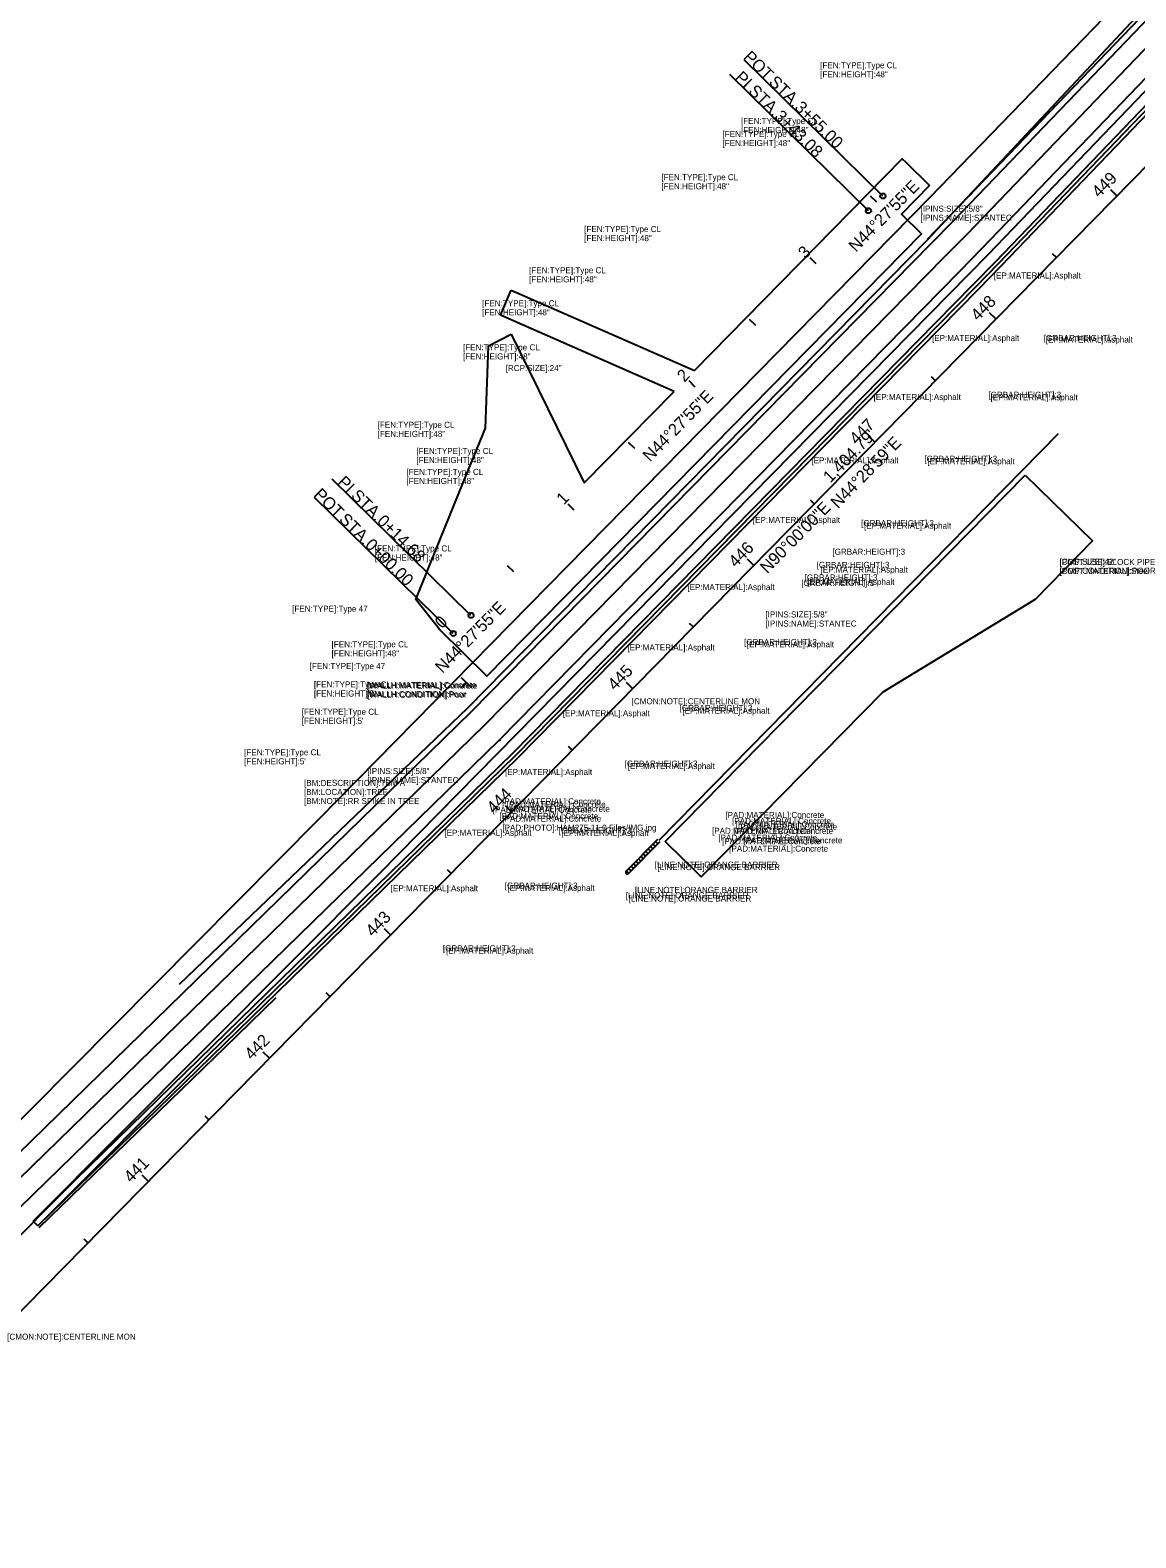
# Model space of a CAD drawing. Extents: x 142554 to 147512, y 370190 to 373751.
# Drawn here: x 144390 to 145029, y 370980 to 371853 of the extents above; entities that cross this region are included whole.
import ezdxf

# ---------------------------------------------------------------- set-up
doc = ezdxf.new("R2010")
doc.units = 0
for name, color, linetype in [('DR_P_Cells', 7, 'Continuous'), ('DR_P_Storm_Sewer', 7, 'Continuous'), ('DR_X_Cells', 7, 'Continuous'), ('DR_X_Ditch', 7, 'Continuous'), ('DR_X_GenericNode', 7, 'Continuous'), ('FeatureService_Stream Network', 7, 'Continuous'), ('FeatureService_Water Bodies', 7, 'Continuous'), ('GE_P_Alignment', 7, 'Continuous'), ('PF_X_Ground_Line', 7, 'Continuous'), ('PM_X_Edge_Line', 7, 'Continuous'), ('PM_X_Lane_Line', 7, 'Continuous'), ('PV_X_EOP', 7, 'Continuous'), ('PV_X_Field_Drive', 7, 'Continuous'), ('PV_X_Shoulder', 7, 'Continuous'), ('RD_X_Fence', 7, 'Continuous'), ('RD_X_GR_Cable_Bar', 7, 'Continuous'), ('RD_X_GR_Lt', 7, 'Continuous'), ('RD_X_GR_Rt', 7, 'Continuous'), ('SC_Scratch20', 7, 'Continuous'), ('UT_X_Electric_Cells', 7, 'Continuous')]:
    doc.layers.add(name, color=color, linetype=linetype)

msp = doc.modelspace()

# ---------------------------------------------------------------- linework, layer by layer
at = {"layer": 'DR_P_Cells'}
for points in [[(144375.11, 371179.46), (144652.68, 371450.31), (144919.03, 371721.55), (144931.96, 371734.79), (145131.57, 371942.86), (145332.92, 372147.7)], [(144383.56, 371170.93), (144661.15, 371441.81), (144927.61, 371713.15), (144940.58, 371726.45), (145140.18, 371934.5), (145341.48, 372139.29)]]:
    msp.add_lwpolyline(points, dxfattribs=at)
at = {"layer": 'DR_P_Storm_Sewer'}
for p, q in [((144734.5, 371365.75), (144752.79, 371384.23)), ((144735.92, 371364.35), (144754.21, 371382.82)), ((144745.78, 371374.31), (144744.36, 371375.71)), ((144747.19, 371375.73), (144745.77, 371377.14)), ((144748.6, 371377.15), (144747.17, 371378.56)), ((144750, 371378.57), (144748.58, 371379.98)), ((144751.41, 371379.99), (144749.99, 371381.4)), ((144752.82, 371381.41), (144751.4, 371382.82)), ((144737.34, 371365.78), (144735.92, 371367.19)), ((144738.75, 371367.2), (144737.33, 371368.61)), ((144740.15, 371368.62), (144738.73, 371370.03)), ((144741.56, 371370.04), (144740.14, 371371.45)), ((144742.97, 371371.46), (144741.55, 371372.87)), ((144744.38, 371372.89), (144742.95, 371374.29)), ((144735.93, 371364.36), (144734.51, 371365.76))]:
    msp.add_line(p, q, dxfattribs=at)
msp.add_arc((144735.22, 371365.05), 1, 135.74249, 315.74249, dxfattribs=at)
at = {"layer": 'DR_X_Cells'}
for p, q in [((144908.94, 371731.25), (145224.54, 372068.86)), ((144908.94, 371731.25), (144642.69, 371460.12)), ((144753.5, 371383.53), (144984.75, 371619.21)), ((144642.69, 371460.12), (144475.78, 371300.04))]:
    msp.add_line(p, q, dxfattribs=at)
at = {"layer": 'DR_X_Ditch'}
for p, q in [((144661.78, 371687.66), (144668.02, 371702.23)), ((144668.02, 371702.23), (144774.04, 371655.59)), ((144762.2, 371643.53), (144661.78, 371687.66)), ((144667.85, 371676.73), (144710.2, 371590.55)), ((144710.2, 371590.55), (144762.2, 371643.53)), ((144757.03, 371382.87), (144965.48, 371595.07))]:
    msp.add_line(p, q, dxfattribs=at)
for points in [[(144774.04, 371655.59), (144894.32, 371778.14), (144896.46, 371776.03), (144910.06, 371762.69), (144893.79, 371746.13), (144905.37, 371734.75), (144653.84, 371478.61), (144626.59, 371505.36), (144612.82, 371523.05), (144626.7, 371557.33), (144640.3, 371591.06), (144653.05, 371622.21), (144654.77, 371669.83), (144667.85, 371676.73)], [(144965.48, 371595.07), (145004.38, 371556.87), (144971.13, 371523.01), (144883.07, 371469.33), (144777.96, 371362.31), (144757.03, 371382.87)]]:
    msp.add_lwpolyline(points, dxfattribs=at)
at = {"layer": 'DR_X_GenericNode'}
msp.add_line((144209.21, 370979.55), (144416.12, 371187.34), dxfattribs=at)
for points in [[(144342.37, 371162.87), (144644.83, 371458.02), (144911.08, 371729.15), (144923.95, 371742.35), (145123.58, 371950.42), (145324.99, 372155.32)], [(144416.12, 371187.34), (144668.82, 371433.92), (144935.38, 371705.37), (144948.4, 371718.72), (145147.98, 371926.75), (145349.23, 372131.49)]]:
    msp.add_lwpolyline(points, dxfattribs=at)
at = {"layer": 'FeatureService_Stream Network'}
msp.add_lwpolyline([(145322.49, 372157.77), (145121.08, 371952.87), (144908.69, 371731.49)], dxfattribs=at)
at = {"layer": 'FeatureService_Water Bodies'}
msp.add_line((144394.01, 371160.17), (144492.32, 371258.89), dxfattribs=at)
msp.add_line((144394.01, 371160.17), (144492.32, 371258.89), dxfattribs=at)
for points in [[(145352.09, 372128.68), (145150.85, 371923.96), (144951.28, 371715.94), (144938.24, 371702.57), (144671.65, 371431.09), (144394.01, 371160.17)], [(145352.09, 372128.68), (145150.85, 371923.96), (144951.28, 371715.94), (144938.24, 371702.57), (144671.65, 371431.09), (144394.01, 371160.17)], [(144492.32, 371258.89), (144670.24, 371432.5), (144936.81, 371703.97), (144949.84, 371717.33), (145149.42, 371925.35), (145350.66, 372130.08)], [(144492.32, 371258.89), (144670.24, 371432.5), (144936.81, 371703.97), (144949.84, 371717.33), (145149.42, 371925.35), (145350.66, 372130.08)]]:
    msp.add_lwpolyline(points, dxfattribs=at)
at = {"layer": 'GE_P_Alignment'}
for p, q in [((144883.06, 371756.67), (144802.77, 371835.47)), ((144874.71, 371748.16), (144794.42, 371826.96)), ((144879.55, 371753.1), (144875.99, 371756.6)), ((144844.53, 371717.42), (144840.96, 371720.92)), ((144809.51, 371681.73), (144805.94, 371685.24)), ((144774.48, 371646.05), (144770.91, 371649.55)), ((144739.46, 371610.37), (144735.89, 371613.87)), ((144644.67, 371513.79), (144564.38, 371592.59)), ((144634.39, 371503.31), (144554.1, 371582.12)), ((144704.44, 371574.68), (144700.87, 371578.19)), ((144669.41, 371539), (144665.84, 371542.5)), ((144634.39, 371503.31), (144630.82, 371506.82)), ((144668.17, 371400.06), (144668.17, 371400.06))]:
    msp.add_line(p, q, dxfattribs=at)
for centre in [(144883.06, 371756.67), (144874.71, 371748.16), (144644.67, 371513.79), (144634.39, 371503.31)]:
    msp.add_circle(centre, 1.5, dxfattribs=at)
at = {"layer": 'PF_X_Ground_Line'}
for p, q in [((144492.32, 371258.89), (144394.01, 371160.17)), ((144394.01, 371160.17), (144391.17, 371162.99))]:
    msp.add_line(p, q, dxfattribs=at)
for points in [[(144391.17, 371162.99), (144591.67, 371364.33), (144944.19, 371723), (145143.68, 371930.93), (145344.96, 372135.69)], [(145350.66, 372130.08), (145149.42, 371925.35), (144949.84, 371717.33), (144936.81, 371703.97), (144670.24, 371432.5), (144492.32, 371258.89)]]:
    msp.add_lwpolyline(points, dxfattribs=at)
at = {"layer": 'PM_X_Edge_Line'}
for p, q in [((144376.23, 371102.81), (145360.57, 372105.07)), ((144661.78, 371441.02), (144661.15, 371441.81))]:
    msp.add_line(p, q, dxfattribs=at)
at = {"layer": 'RD_X_GR_Cable_Bar'}
for p, q in [((145018.52, 371756.79), (145014.95, 371760.29)), ((144983.48, 371721.12), (144981.34, 371723.22)), ((144948.45, 371685.44), (144944.88, 371688.95)), ((144913.41, 371649.77), (144911.27, 371651.87)), ((144878.38, 371614.1), (144874.81, 371617.6)), ((144843.34, 371578.42), (144841.2, 371580.53)), ((144808.31, 371542.75), (144804.74, 371546.25)), ((144773.27, 371507.08), (144771.13, 371509.18)), ((144738.24, 371471.41), (144734.67, 371474.91)), ((144703.2, 371435.73), (144701.06, 371437.83)), ((144668.17, 371400.06), (144664.6, 371403.56)), ((144633.13, 371364.39), (144630.99, 371366.49)), ((144598.1, 371328.71), (144594.53, 371332.22)), ((144563.06, 371293.04), (144560.92, 371295.14)), ((144528.03, 371257.37), (144524.46, 371260.87)), ((144492.99, 371221.7), (144490.85, 371223.8)), ((144457.96, 371186.02), (144454.39, 371189.53)), ((144422.92, 371150.35), (144420.78, 371152.45))]:
    msp.add_line(p, q, dxfattribs=at)
at = {"layer": 'RD_X_GR_Lt'}
for p, q in [((144639, 371477.76), (144644.7, 371472.16)), ((144641.85, 371474.96), (144639.05, 371472.11)), ((144641.85, 371474.96), (144641.85, 371474.96))]:
    msp.add_line(p, q, dxfattribs=at)
at = {"layer": 'RD_X_GR_Rt'}
for p, q in [((144502.3, 371263.68), (144531.91, 371292.44)), ((144394.69, 371159.19), (144502.3, 371263.68))]:
    msp.add_line(p, q, dxfattribs=at)
at = {"layer": 'SC_Scratch20'}
msp.add_lwpolyline([(144176.13, 371012.23), (144556.99, 371396.08), (144910.51, 371755.96), (145111.72, 371964.03), (145312.15, 372167.94)], dxfattribs=at)

# ---------------------------------------------------------------- texts
at = {"layer": 'GE_P_Alignment'}
for s, rotation, p in [('POT', 315.53484, (144801.84, 371836.54)), ('PI', 315.53484, (144796.9, 371824.67)), (' STA. ', 315.53484, (144802.95, 371818.73)), (' STA. ', 315.53484, (144814.68, 371823.93)), ('3+43.08', 315.53484, (144819.82, 371802.18)), ('3+55.00', 315.53484, (144831.55, 371807.37)), ('N44°27\'55"E', 45.53484, (144867.55, 371723.74)), ('3', 45.53484, (144838.25, 371719.95)), ('2', 45.53484, (144768.19, 371648.56)), ('N44°27\'55"E', 45.53484, (144748.35, 371602.3)), ('PI', 315.53484, (144566.87, 371590.3)), ('POT', 315.53484, (144553.17, 371583.18)), (' STA. ', 315.53484, (144572.92, 371584.36)), ('1', 45.53484, (144698.37, 371577.43)), ('N90°00\'00"E', 45.51119, (144816.21, 371537.62)), (' STA. ', 315.53484, (144566.01, 371570.57)), ('0+14.68', 315.53484, (144589.78, 371567.81)), ('0+00.00', 315.53484, (144582.88, 371554.02)), ('N44°27\'55"E', 45.53484, (144628.19, 371479.87)), ('0', 45.53484, (144627.98, 371505.71))]:
    msp.add_text(s, height=7, rotation=rotation, dxfattribs=at).set_placement(p)
at = {"layer": 'PM_X_Lane_Line'}
msp.add_text('N44°28\'59"E', height=7, rotation=45.5169, dxfattribs=at).set_placement((144857.06, 371575.26))
at = {"layer": 'PV_X_EOP'}
for s, p in [('[FEN:TYPE]:Type CL', (144846.8, 371830.66)), ('[FEN:HEIGHT]:48"', (144846.8, 371825.41)), ('[FEN:TYPE]:Type CL', (144790.23, 371790.85)), ('[FEN:TYPE]:Type CL', (144800.94, 371798.42)), ('[FEN:HEIGHT]:48"', (144800.94, 371793.17)), ('[FEN:HEIGHT]:48"', (144790.23, 371785.6)), ('[FEN:TYPE]:Type CL', (144754.87, 371765.83)), ('[FEN:HEIGHT]:48"', (144754.87, 371760.58)), ('[FEN:TYPE]:Type CL', (144710.22, 371735.77)), ('[FEN:HEIGHT]:48"', (144710.22, 371730.52)), ('[FEN:TYPE]:Type CL', (144678.28, 371711.93)), ('[FEN:HEIGHT]:48"', (144678.28, 371706.68)), ('[EP:MATERIAL]:Asphalt', (144947.26, 371708.89)), ('[FEN:TYPE]:Type CL', (144651.17, 371692.82)), ('[FEN:HEIGHT]:48"', (144651.17, 371687.57)), ('[EP:MATERIAL]:Asphalt', (144911.49, 371672.62)), ('[GRBAR:HEIGHT]:3', (144976.26, 371672.7)), ('[EP:MATERIAL]:Asphalt', (144977.31, 371671.81)), ('[FEN:TYPE]:Type CL', (144640.03, 371667.26)), ('[FEN:HEIGHT]:48"', (144640.03, 371662.01)), ('[RCP:SIZE]:24"', (144664.74, 371655.29)), ('[EP:MATERIAL]:Asphalt', (144877.7, 371638.52)), ('[GRBAR:HEIGHT]:3', (144944.14, 371639.79)), ('[EP:MATERIAL]:Asphalt', (144945.42, 371638.36)), ('[FEN:TYPE]:Type CL', (144590.64, 371622.41)), ('[FEN:HEIGHT]:48"', (144590.64, 371617.16)), ('[FEN:TYPE]:Type CL', (144613.01, 371607.27)), ('[FEN:HEIGHT]:48"', (144613.01, 371602.02)), ('[EP:MATERIAL]:Asphalt', (144841.69, 371601.8)), ('[GRBAR:HEIGHT]:3', (144907.09, 371602.74)), ('[EP:MATERIAL]:Asphalt', (144908.9, 371601.34)), ('[FEN:TYPE]:Type CL', (144607.32, 371595.15)), ('[FEN:HEIGHT]:48"', (144607.32, 371589.9)), ('[EP:MATERIAL]:Asphalt', (144807.84, 371567.34)), ('[GRBAR:HEIGHT]:3', (144870.47, 371565.47)), ('[EP:MATERIAL]:Asphalt', (144872.12, 371563.95)), ('[FEN:TYPE]:Type CL', (144589.06, 371550.82)), ('[GRBAR:HEIGHT]:3', (144853.83, 371548.9)), ('[FEN:HEIGHT]:48"', (144589.06, 371545.57)), ('[GRBAR:HEIGHT]:3', (144844.74, 371541.29)), ('[EP:MATERIAL]:Asphalt', (144847, 371538.56)), ('[POST:USE]:BLOCK PIPE', (144985.34, 371542.96)), ('[POST:MATERIAL]:Steel', (144985.34, 371537.71)), ('[CMP:SIZE]:42"', (144985.38, 371543.18)), ('[CMP:CONDITION]:POOR', (144985.38, 371537.93)), ('[GRBAR:HEIGHT]:3', (144835.84, 371530.87)), ('[GRBAR:HEIGHT]:3', (144837.82, 371533.99)), ('[EP:MATERIAL]:Asphalt', (144839.3, 371531.47)), ('[EP:MATERIAL]:Asphalt', (144769.92, 371528.41)), ('[FEN:TYPE]:Type 47', (144541.18, 371515.89)), ('[FEN:TYPE]:Type CL', (144563.99, 371495.31)), ('[GRBAR:HEIGHT]:3', (144802.72, 371496.61)), ('[EP:MATERIAL]:Asphalt', (144804.34, 371495.3)), ('[FEN:HEIGHT]:48"', (144563.99, 371490.06)), ('[EP:MATERIAL]:Asphalt', (144735.24, 371493.47)), ('[FEN:TYPE]:Type 47', (144551.32, 371482.67)), ('[FEN:TYPE]:Type CL', (144553.76, 371472.04)), ('[WALLH:MATERIAL]:Concrete', (144584.14, 371471.7)), ('[WALLH:MATERIAL]:Concrete', (144584.71, 371471.31)), ("[FEN:HEIGHT]:5'", (144553.76, 371466.79)), ('[WALLH:CONDITION]:Poor', (144584.14, 371466.45)), ('[WALLH:CONDITION]:Poor', (144584.71, 371466.06)), ('[FEN:TYPE]:Type CL', (144546.72, 371456.22)), ("[FEN:HEIGHT]:5'", (144546.72, 371450.97)), ('[EP:MATERIAL]:Asphalt', (144697.75, 371455.39)), ('[GRBAR:HEIGHT]:3', (144765.42, 371458.46)), ('[EP:MATERIAL]:Asphalt', (144767.03, 371456.84)), ('[FEN:TYPE]:Type CL', (144513.35, 371432.76)), ("[FEN:HEIGHT]:5'", (144513.35, 371427.51)), ('[GRBAR:HEIGHT]:3', (144733.63, 371426.2)), ('[EP:MATERIAL]:Asphalt', (144735.39, 371424.78)), ('[EP:MATERIAL]:Asphalt', (144664.33, 371421.37)), ('[PAD:MATERIAL]:Concrete', (144657.29, 371399.53)), ('[PAD:MATERIAL]:Concrete', (144662.65, 371404.38)), ('[PAD:MATERIAL]:Concrete', (144665.42, 371402.58)), ('[PAD:MATERIAL]:Concrete', (144667.78, 371400.03)), ('[PAD:MATERIAL]:Concrete', (144661.04, 371395.84)), ('[PAD:MATERIAL]:Concrete', (144662.84, 371394.35)), ('[PAD:PHOTO]:HAM275-11.0 Files/IMG.jpg', (144662.84, 371389.1)), ('[PAD:MATERIAL]:Concrete', (144791.9, 371396.45)), ('[PAD:MATERIAL]:Concrete', (144795.8, 371393.01)), ('[PAD:MATERIAL]:Concrete', (144797.84, 371391)), ('[PAD:MATERIAL]:Concrete', (144799.34, 371389.57)), ('[EP:MATERIAL]:Asphalt', (144629.28, 371386.13)), ('[GRBAR:HEIGHT]:3', (144695.51, 371387.49)), ('[EP:MATERIAL]:Asphalt', (144696.94, 371386.04)), ('[PAD:MATERIAL]:Concrete', (144784.17, 371387.28)), ('[PAD:MATERIAL]:Concrete', (144787.81, 371383.38)), ('[PAD:MATERIAL]:Concrete', (144789.97, 371381.25)), ('[PAD:MATERIAL]:Concrete', (144797.03, 371387.16)), ('[PAD:MATERIAL]:Concrete', (144802.42, 371381.77)), ('[PAD:MATERIAL]:Concrete', (144794.13, 371376.97)), ('[LINE:NOTE]:ORANGE BARRIER', (144751.12, 371367.71)), ('[LINE:NOTE]:ORANGE BARRIER', (144752.56, 371366.24)), ('[EP:MATERIAL]:Asphalt', (144598.26, 371354)), ('[GRBAR:HEIGHT]:3', (144664.24, 371355.55)), ('[EP:MATERIAL]:Asphalt', (144665.72, 371354.18)), ('[LINE:NOTE]:ORANGE BARRIER', (144734.27, 371349.88)), ('[LINE:NOTE]:ORANGE BARRIER', (144735.91, 371348.08)), ('[LINE:NOTE]:ORANGE BARRIER', (144739.56, 371353.08)), ('[GRBAR:HEIGHT]:3', (144628.42, 371319.25)), ('[EP:MATERIAL]:Asphalt', (144630.24, 371317.93))]:
    msp.add_text(s, height=3.5, dxfattribs=at).set_placement(p)
at = {"layer": 'PV_X_Field_Drive'}
for s, p in [('[IPINS:SIZE]:5/8"', (144904.86, 371747.59)), ('[IPINS:SIZE]:5/8"', (144904.86, 371747.59)), ('[IPINS:NAME]:STANTEC', (144904.86, 371742.34)), ('[IPINS:NAME]:STANTEC', (144904.86, 371742.34)), ('[IPINS:SIZE]:5/8"', (144815.06, 371512.57)), ('[IPINS:NAME]:STANTEC', (144815.06, 371507.32)), ('[IPINS:SIZE]:5/8"', (144584.65, 371421.88)), ('[IPINS:SIZE]:5/8"', (144584.65, 371421.88)), ('[IPINS:NAME]:STANTEC', (144584.65, 371416.63)), ('[IPINS:NAME]:STANTEC', (144584.65, 371416.63))]:
    msp.add_text(s, height=3.5, dxfattribs=at).set_placement(p)
at = {"layer": 'PV_X_Shoulder'}
for p in [(144737.65, 371462.31), (144376.23, 371094.31)]:
    msp.add_text('[CMON:NOTE]:CENTERLINE MON', height=3.5, dxfattribs=at).set_placement(p)
at = {"layer": 'RD_X_Fence'}
msp.add_text("1,404.79'", height=7, rotation=45.5169, dxfattribs=at).set_placement((144852.67, 371590.14))
at = {"layer": 'RD_X_GR_Cable_Bar'}
for s, p in [('449', (145008.24, 371755.25)), ('448', (144938.14, 371683.87)), ('447', (144867.93, 371612.38)), ('446', (144797.96, 371541.14)), ('445', (144727.99, 371469.89)), ('444', (144657.98, 371398.6)), ('443', (144587.91, 371327.26)), ('442', (144517.82, 371255.9)), ('441', (144447.98, 371184.78))]:
    msp.add_text(s, height=7, rotation=45.5169, dxfattribs=at).set_placement(p)
at = {"layer": 'UT_X_Electric_Cells'}
for s, p in [('[BM:DESCRIPTION]:TBM A', (144548.04, 371415.04)), ('[BM:LOCATION]:TREE', (144548.04, 371409.79)), ('[BM:NOTE]:RR SPIKE IN TREE', (144548.04, 371404.54))]:
    msp.add_text(s, height=3.5, dxfattribs=at).set_placement(p)

doc.saveas('drawing.dxf')
